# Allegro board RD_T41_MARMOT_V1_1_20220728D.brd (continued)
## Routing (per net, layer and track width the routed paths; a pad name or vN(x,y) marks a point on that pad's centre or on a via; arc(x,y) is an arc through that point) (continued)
SFC1_WP_IO2: length 24.6
  TOP w0.102: U6.U7 62.19,43.18 62.19,29.52 65.24,26.47 65.24,21.68 65.61,21.31 R167.1 66.41,21.31 R72.1
SFC_CS_N: length 27.2
  TOP w0.102: R26.1 52.27,22.46 51.04,23.68 51.04,27.13 51.88,27.97 U7.1 53.4,27.97 54.08,28.64 54.08,31.89 59.61,37.42 59.61,41.56 60.01,41.96 60.01,43.81 U6.T4
SFC_SCLK: length 22.9
  TOP w0.102: U6.R6 61.09,44.24 61.09,41.09 60.73,40.73 60.73,35.81 57.44,32.52 57.44,26.41 58.43,25.43 U7.6
SFC_SIO0: length 23.6
  TOP w0.102: U7.5 57.85,24.16 56.54,25.47 56.54,33.01 60.27,36.73 60.27,41.29 60.7,41.72 60.7,43.2 U6.U5
SFC_SIO1: length 21.9
  TOP w0.102: U6.R5 60.45,44.24 60.45,43.75 60.24,43.55 60.24,41.89 59.82,41.47 59.82,37.14 54.88,32.2 54.88,27.67 53.91,26.7 U7.2
SFC_SIO2: length 22.8
  TOP w0.102: U6.T5 60.79,43.75 60.46,43.42 60.46,41.77 60.03,41.34 60.03,36.9 55.73,32.6 55.73,26.73 54.42,25.43 U7.3
SFC_SIO3: length 19.7
  TOP w0.102: U6.T6 61.3,43.79 61.3,42.95 61.45,42.79 61.45,35.34 58.54,32.43 58.54,27.46 59.3,26.7 U7.7
SLCD_BLEN: length 3.5
  TOP w0.102: U24.16 108.39,66.74 ; 108.39,66.74 108.39,67.1 108.53,67.24 U24.15 ; 108.39,66.74 R276.1 106.75,66.06 R81.1
SLCD_BT656_D0: length 60.2
  TOP w0.102: R253.1 112.86,79.83 111.68,79.83 110.9,80.62 90.25,80.62 67.38,57.75 67.38,53.78 U6.A15
SLCD_BT656_D1: length 60.8
  TOP w0.102: R256.1 112.88,78.84 110.78,78.84 109.3,80.32 90.24,80.32 67.62,57.7 67.62,53.57 67.29,53.24 U6.B15
SLCD_BT656_D2: length 59.7
  TOP w0.102: R259.1 112.95,77.89 111.32,77.89 109.32,79.89 90.14,79.89 67.94,57.68 U6.A16
SLCD_BT656_D3: length 59.1
  TOP w0.102: R263.1 112.9,76.83 111.42,76.83 110.67,76.08 86.7,76.08 68.25,57.62 68.25,53.54 68.08,53.37 67.82,53.37 67.59,53.14 67.59,52.69 U6.C15
SLCD_BT656_D4: length 56.5
  TOP w0.102: R264.1 112.88,75.79 86.8,75.79 68.59,57.57 U6.A17
SLCD_BT656_D5: length 57.1
  TOP w0.102: U6.B16 68.16,53.03 68.46,53.34 68.88,53.34 68.99,53.45 68.99,57.61 86.19,74.81 112.92,74.81 R266.1
SLCD_BT656_D6: length 56.1
  TOP w0.102: U6.B17 68.96,53.03 69.26,53.33 69.26,57.52 85.55,73.8 112.92,73.8 R269.1
SLCD_BT656_D7: length 57.4
  TOP w0.102: R272.1 112.84,72.7 109.73,72.7 108.87,73.56 85.61,73.56 69.61,57.56 69.61,53.27 69.07,52.73 68.28,52.73 U6.C16
SLCD_CS: length 64.6
  TOP w0.102: R277.1 TP27.1 109.47,86.08 107.83,84.44 107.83,84.45 93.12,84.45 74.78,66.11 73.06,66.11 71.93,64.98 71.93,63.8 66.45,58.32 66.45,54.24 66.32,54.1 66.32,53.57 65.99,53.24 U6.B13
SLCD_CS_PD10: length 4.5
  TOP w0.102: J22.14 116.33,87.95 R277.2
SLCD_D0_PD00: length 4.6
  TOP w0.102: R253.2 114.8,80.39 116.75,78.45 J22.33
SLCD_D1_PD01: length 4.3
  TOP w0.102: R250.2 114.73,79.38 116.16,77.95 J22.34
SLCD_D2_PD02: length 4.1
  TOP w0.102: R258.2 114.69,78.36 115.6,77.45 J22.35
SLCD_D3_PD03: length 3.9
  TOP w0.102: R261.2 114.85,76.95 J22.36
SLCD_D4_PD04: length 3.8
  TOP w0.102: R262.2 114.57,76.45 J22.37
SLCD_D5_PD05: length 4
  TOP w0.102: J22.38 115.09,75.95 R266.2
SLCD_D6_PD06: length 4.2
  TOP w0.102: J22.39 115.97,75.45 114.81,74.29 R269.2
SLCD_D7_PD07: length 4.4
  TOP w0.102: J22.40 116.62,74.95 114.95,73.28 R271.2
SLCD_DC: length 65.8
  TOP w0.102: U6.C13 65.67,52.7 65.67,54.1 65.97,54.4 65.97,58.55 71.42,64 71.42,65.3 72.77,66.65 74.6,66.65 93.17,85.22 v1(106.92,85.22) ; R278.1 111.61,85.09 TP28.1 v1(109.06,85.06)
  BOTTOM w0.102: v1(109.06,85.06) 108.9,85.22 v1(106.92,85.22)
SLCD_DC_PD11: length 5
  TOP w0.102: R278.2 114.98,85.61 114.98,86.09 116.34,87.45 J22.15
SLCD_IOVDD: length 1.7
  BOTTOM w0.305: v1(116.96,91.7) 117.07,91.59 C198.1 C200.1
SLCD_LEDA: length 9.3
  TOP w0.279: 116.76,73.45 J22.43 ; 112.3,68.24 U24.8
  TOP w0.381: 112.3,68.24 112.8,68.24 C201.1 113.28,68.72 113.28,69.96 116.76,73.45
SLCD_LEDK: length 9.9
  TOP w0.249: U24.6 112.25,67.24 112.58,66.91 ; U24.5 112.5,66.74
  TOP w0.279: J22.47 116.83,71.45 ; J22.46 116.83,71.95 ; 116.87,72.76 117.06,72.95 J22.44 ; J22.45 116.83,72.45 ; J22.49 116.83,70.45 ; J22.48 116.83,70.95
SLCD_RDY: length 64.3
  TOP w0.102: U6.C14 66.29,52.73 66.29,53.12 66.53,53.36 66.53,53.99 66.67,54.13 66.67,58.21 72.26,63.8 72.26,64.98 73.16,65.88 74.88,65.88 93.1,84.1 TP29.1 110.01,84.09 R279.1
SLCD_RDY_PD12: length 5.4
  TOP w0.102: J22.17 v1(116.97,86.45) 116.82,86.45 R279.2
  BOTTOM w0.102: R257.1 116.96,86.47 v1(116.97,86.45)
SLCD_RST_PD09: length 4.3
  TOP w0.102: R275.2 114.78,87.08 116.15,88.45 J22.13
SLCD_TE: length 64.6
  TOP w0.102: R275.1 111.58,87.08 TP26.1 110.06,87.08 107.81,84.82 93.14,84.82 74.7,66.39 72.96,66.39 71.69,65.12 71.69,63.91 66.21,58.43 66.21,54.31 65.99,54.09 U6.A13
SLCD_VCI: length 1.6
  BOTTOM w0.305: C199.1 117.63,89.79 C197.1 116.97,90.68 v1(116.96,90.7)
SLCD_WR_BT656_PCLK: length 62
  TOP w0.102: U6.B14 66.75,53.14 66.75,53.91 66.89,54.06 66.89,58.13 72.5,63.74 72.5,64.87 73.25,65.61 74.91,65.61 90.25,80.95 112.92,80.95 112.94,80.93 R274.1
SLCD_WR_PD08: length 8.2
  TOP w0.102: v1(115.5,85.76) 115.5,86.04 116.41,86.95 J22.16 ; R273.2 v1(114.45,82.13)
  BOTTOM w0.102: v1(115.5,85.76) 114.45,84.71 v1(114.45,82.13)
SOC_0V8: length 52.7
  TOP w0.508: v1(79.07,47.35) 79.03,47.35 78.36,46.67 78.36,41.26 v1(77.36,40.26)
  BOTTOM w0.254: C16.1 84.81,54.49 C15.2 85.54,54.48 R6.2
  BOTTOM w0.508: J4.1 79.67,47.94 v1(79.07,47.35) ; 62.41,37.07 61.72,37.76 ; 62.41,37.07 61.56,37.07 ; 62.41,37.07 64.12,35.36 72.46,35.36 v1(77.36,40.26) ; 61.72,37.76 61.72,37.22 61.56,37.07 ; 61.72,37.76 R325.1 ; 61.56,37.07 53.27,37.07 52.06,38.28 R330.2
SOC_1V8: length 72.2
  TOP w0.33: v1(58.41,39.04) 58.41,39.27 58.42,39.29 R27.2
  L3_PWR w0.508: v1(53.51,38.1) 53.15,38.47 v1(51.24,38.47) ; v1(58.41,39.04) 58.65,39.28 66.83,39.28 69.67,36.44 71.36,36.44 v1(71.58,36.65)
  BOTTOM w0.381: v1(58.41,39.04) 58.74,38.71 R326.1
  BOTTOM w0.508: R84.1 55.75,55.29 55.75,57.37 56.31,57.93 60.9,57.93 R80.1 ; R84.1 v1(54.13,54.95) v1(53.82,55.26) ; R84.1 53.73,53.26 53.73,48.84 R331.2 ; R28.2 64.57,39.99 65.81,38.76 67.55,38.76 69.69,36.62 71.55,36.62 v1(71.58,36.65) 72.19,37.26 R329.1 ; R328.1 53.29,38.32 v1(53.51,38.1) 53.68,37.94 58.65,37.94 59.04,38.32 R326.1 ; R331.2 53.09,48.62 50.43,45.97 50.43,39.28 v1(51.24,38.47) ; R331.2 55.07,48.62 R44.1
SOC_3V3: length 54.3
  TOP w0.254: R60.2 v1(71.58,37.56) ; R56.2 v1(69.9,37.21)
  TOP w0.305: TP3.1 36.78,64.56 J3.2 36.78,69.42 R16.1
  L3_PWR w0.508: v1(49.37,57.31) 49.37,57.1 v1(49.66,56.8) 53.16,56.8 53.64,56.32 56.17,56.32 56.65,56.8 58.6,56.8 v1(58.67,56.88) ; v1(71.58,37.56) 71.23,37.21 v1(69.9,37.21) 69.81,37.21 67.1,39.92 v1(63.21,39.92) 55.41,39.92 v1(54.96,39.47) 50.36,39.47 v1(49.79,38.9)
  BOTTOM w0.305: R63.2 63.31,40.02 v1(63.21,39.92)
  BOTTOM w0.381: R58.2 66.1,42.68 R57.2 65.46,41.22 65.46,40.09 66.1,39.44 67.66,39.44 v1(69.9,37.21) 71.23,37.21 v1(71.58,37.56)
  BOTTOM w0.508: v1(58.67,56.88) R64.2 ; R327.1 v1(54.96,39.47)
SOC_DDR: length 2.3
  TOP w0.381: TP5.1 77.02,59.93 J5.2
SPEAK_EN_PB31: length 118.2
  TOP w0.102: R103.1 34.06,16.42 v1(46.53,28.89) ; v1(76.95,88.87) 76.39,88.3 76.39,84.07 74.65,82.33 74.65,75.97 71.55,72.87 70.66,72.87 70.01,72.22 68.41,72.22 63.8,67.62 v1(63.8,64.39) 63.8,63.18 64.12,62.86 64.12,53.12 U6.B10 ; R187.1 v1(71.21,88.41)
  BOTTOM w0.102: v1(63.8,64.39) 63.06,64.39 62.48,63.81 50,63.81 46.86,60.67 46.86,29.21 v1(46.53,28.89) ; v1(71.21,88.41) 71.77,88.97 76.85,88.97 v1(76.95,88.87)
SPI1_CLK: length 6
  TOP w0.102: R206.1 67.67,18.1 67.67,21.19 68.4,21.92 R120.2
SPI1_CLK_PA22: length 3.2
  TOP w0.102: R206.2 65.68,15.08 65.18,15.08 64.81,14.71 U21.26
SPI1_CS: length 3.6
  TOP w0.102: R123.2 64.59,19.02 65.75,17.86 65.75,17.2 R208.1
SPI1_CS_PA29: length 3
  TOP w0.102: R208.2 65.78,15.69 65.4,15.31 65.05,15.31 64.31,14.57 U21.27
SPI1_DR: length 7
  TOP w0.102: v1(64.11,19.38) 64.11,18.8 64.83,18.07 R203.1 ; v1(65.28,19.35) 65.12,19.52 65.12,21.5 64.78,21.83 R67.2
  BOTTOM w0.102: v1(65.28,19.35) 64.14,19.35 v1(64.11,19.38)
SPI1_DR_PA21: length 2.5
  TOP w0.102: U21.28 63.81,15.06 R203.2
SPI1_DT: length 9.1
  TOP w0.102: R200.1 63.9,18.47 v1(63.8,18.58) ; R82.2 66.76,22.26 67.38,21.65 67.38,18.7 v1(67.25,18.58)
  BOTTOM w0.102: v1(63.8,18.58) v1(67.25,18.58)
SPI1_DT_PA20: length 2.4
  TOP w0.102: U21.29 63.31,15.48 R200.2
SPK_OUTL: length 10.7
  TOP w0.249: U17.28 65.59,85.22 65.72,85.35
  TOP w0.305: 65.72,85.35 66.7,86.33 73.92,86.33 C154.1
SPKOUT_N: length 8.6
  TOP w0.33: U11.8 v1(32.71,6.88) D8.2 32.45,6.11 J10.1
  BOTTOM w0.33: R101.1 29.78,8.96 31.86,6.88 v1(32.71,6.88)
SPKOUT_P: length 6.2
  TOP w0.33: U11.5 v1(30.76,6.98) D9.2 31.2,6.17 J10.2
  BOTTOM w0.33: R95.1 29.71,8.04 v1(30.76,6.98)
STO: length 4.2
  TOP w0.102: TP55.1 56.75,80.88 U17.6
TD_N: length 46.3
  TOP w0.102: U6.U16 68,43.22 68,42.89 68.64,42.25 70.28,42.25 73.96,38.58 73.96,38.41 73.89,38.34 73.89,38.17 74.01,38.05 74.17,38.05 74.24,38.12 74.41,38.12 74.53,38 74.53,37.83 74.41,37.71 74.41,37.54 74.53,37.42 74.7,37.42 74.82,37.54 74.99,37.54 75.11,37.43 75.11,37.26 74.98,37.13 74.98,36.97 75.1,36.85 75.27,36.85 75.39,36.97 75.56,36.97 89.38,23.15 89.38,19.99 v1(89.26,19.86) ; R240.1 v1(93.91,12.77)
  BOTTOM w0.102: v1(89.26,19.86) 89.61,20.22 90.29,20.22 90.71,19.8 90.71,14.96 93.21,12.46 93.6,12.46 v1(93.91,12.77)
TD_P: length 46.4
  TOP w0.102: U6.T16 68.28,43.59 68.28,43 68.76,42.53 70.4,42.53 89.66,23.26 89.66,19.99 v1(89.79,19.86) ; R238.1 v1(93.91,11.87)
  BOTTOM w0.102: v1(89.79,19.86) 89.94,20.01 90.1,20.01 90.43,19.68 90.43,18.36 90.32,18.24 90.19,18.24 90.07,18.12 90.07,17.95 90.19,17.83 90.32,17.83 90.43,17.72 90.43,17.55 90.32,17.43 90.19,17.43 90.07,17.31 90.07,17.14 90.19,17.02 90.32,17.02 90.43,16.9 90.43,16.73 90.32,16.62 90.19,16.62 90.07,16.5 90.07,16.33 90.19,16.21 90.32,16.21 90.43,16.09 90.43,14.84 93.09,12.18 93.6,12.18 v1(93.91,11.87)
TEST_TE: length 2.4
  TOP w0.102: U6.L13 v1(66.96,46.21)
  BOTTOM w0.102: v1(66.96,46.21) 66.96,46.18 TP8.1
TX+: length 25.2
  TOP w0.254: J19.1 117.47,18.99 117.76,18.78 118.26,18.78 119.78,17.27 119.78,12.58 117.55,10.36 114.47,10.36 112.65,12.18 106.92,12.18 105.79,11.05 U23.9
TX-: length 25.2
  TOP w0.254: U23.11 105.98,13.59 106.79,12.78 108.37,12.78 108.74,13.16 109.39,13.16 109.76,12.78 112.85,12.78 114.75,10.88 117.35,10.88 119.27,12.79 119.27,17.05 118.07,18.25 115.77,18.25 J19.2
TX_N0: length 8.1
  TOP w0.102: U22.4 84.68,15.2 84.79,15.09 87.7,15.09 90.33,12.46 90.95,12.46 R214.1
TX_P0: length 8.1
  TOP w0.102: U22.3 84.68,14.7 84.79,14.81 87.58,14.81 90.21,12.18 90.95,12.18 R213.1
U0_RTS_PB21: length 98.1
  TOP w0.102: v1(97.51,70.77) 97.42,70.86 83.85,70.86 v1(83.76,70.76) ; TP22.1 98.84,53.02 v1(98.05,53.02) 97.61,53.02 97.06,53.57 93.96,53.57 93.42,53.04 69.73,53.04 69.08,52.38 U6.C17
  BOTTOM w0.102: v1(97.51,70.77) 97.51,53.56 v1(98.05,53.02) ; R76.1 55.36,74.83 61.97,68.22 66.04,68.22 68.12,66.14 72.77,66.14 77.4,70.76 v1(83.76,70.76)
U0_TXD_PB22: length 77.8
  TOP w0.102: v1(96.58,69.23) 96.52,69.28 v1(82.33,69.28) ; U6.D15 67.62,52.07 69.06,52.07 69.82,52.83 93.51,52.83 93.98,53.29 96.75,53.29 v1(97.12,52.92) TP23.1 ; R68.1 v1(69.56,64.76)
  BOTTOM w0.102: v1(69.56,64.76) 69.78,64.98 73.09,64.98 77.4,69.28 v1(82.33,69.28) ; v1(97.12,52.92) 97.28,53.08 97.28,68.53 v1(96.58,69.23)
UART1_RXD_PB24: length 51.4
  TOP w0.102: U6.F16 68.05,50.54 110.56,50.54 114.44,54.42 116.22,54.42 R292.2 R289.2
UART1_TXD_PB23: length 52.2
  TOP w0.102: U6.F15 67.62,50.77 110.47,50.77 114.35,54.65 116.18,54.65 R293.2 116.63,55.1 R290.2
USB_AVD08: length 3.1
  TOP w0.254: U6.R4 v1(59.81,44.26)
  BOTTOM w0.254: v1(59.81,44.26) 59.81,43.99 C74.1 61.1,43.62 C73.1 62.02,43.62 FB4.2
USB_AVD18: length 4.5
  TOP w0.254: U6.T3 v1(59.16,43.61)
  BOTTOM w0.305: v1(59.16,43.61) 59.14,43.59 59.14,41.89 C76.1
  BOTTOM w0.381: FB2.2 59.36,39.72 C77.1 59.36,41.67 C76.1
USB_AVD33: length 5.4
  TOP w0.254: U6.R3 v1(59.16,44.26)
  BOTTOM w0.305: C78.1 58.42,41.68 58.73,41.99 58.73,43.1 58.68,43.15 58.68,43.78 v1(59.16,44.26)
  BOTTOM w0.381: FB5.2 58.28,39.85 C79.1 58.28,40.78 C78.1
USB_DM: length 7
  TOP w0.13: R151.1 55.78,38.69 56.28,39.2 56.28,39.42 55.99,39.71 55.99,39.92 56.15,40.07 56.36,40.07 56.65,39.78 56.87,39.78 57.06,39.98 57.06,42.05 58.21,43.2 58.21,43.26 U6.U1
USB_DP: length 7
  TOP w0.13: U6.T2 58.51,43.61 58.51,43.07 57.37,41.93 57.37,39.85 56.09,38.58 R152.1
USB_ID: length 2.5
  TOP w0.102: R27.1 58.42,41.9 58.84,42.31 U6.U2
USB_VBUS: length 8.2
  TOP w0.254: U6.U3 59.18,42.98 59.18,42.21 59.01,42.03 59.01,38.91 57.34,37.24 R25.1
  TOP w0.381: R25.1 56.99,37.22 57.61,36.6
VCM: length 2.5
  TOP w0.254: U6.R2 v1(58.51,44.26)
  BOTTOM w0.305: C68.1 56.72,43.7 C67.1 57.95,43.7 v1(58.51,44.26)
WIFI_WAKE_HOST: length 10.8
  TOP w0.102: TP45.1 61.69,62.87 61.69,54.18 61.44,53.92 U6.B6
WKUP_PD31: length 15.5
  TOP w0.102: TP11.1 81.26,45.37 81.26,46.73 79.58,48.42 68.65,48.42 U6.J17
XTO: length 2.8
  TOP w0.102: TP53.1 61.59,76.28 U17.10
N14970173: length 3.5
  TOP w0.203: R2.2 31.64,86.2 C7.2 31.63,87.19 R3.2 31.64,88.19 U1.3
N15664622: length 2.1
  TOP w0.381: U1.4 C6.1 32.82,91.64 R1.2
N16749111: length 15.1
  TOP w0.203: R24.1 60.41,22.46 R26.2
  TOP w0.381: U7.8 61.09,27.97 62.11,26.96 C60.1 62.11,26.26 C64.1 62.11,23.2 R24.1
N16751575: length 4.8
  TOP w0.102: R32.1 54.43,52.36 52.34,52.36 Y2.3 50.92,51.7 C70.2
N16753264: length 14.1
  TOP w0.102: C75.1 12.71,64.18 R33.2 ; C75.1 11.68,63.18 11.68,62.05 10.68,61.05 SW1.5 SW1.1 ; C75.1 12.69,65.05 R34.1
N16757380: length 3.8
  TOP w0.102: R39.1 86.42,39.41 R37.1
N16760505: length 36.2
  TOP w0.13: R151.2 54.72,37.54 48.98,31.8 48.98,10.23 TP13.1 48.98,9.71 48.98,7.38 D3.2 48.98,6.48 48.98,5.8 48.81,5.63 J7.2
N16760513: length 36.2
  TOP w0.13: J7.3 49.46,5.63 49.29,5.8 49.29,6.48 D5.2 49.29,7.38 49.29,9.71 TP12.1 49.29,10.23 49.29,31.67 52.56,34.95 52.78,34.95 52.79,34.94 53,34.94 53.16,35.09 53.16,35.3 53.14,35.32 53.14,35.53 54.94,37.32 55.36,37.32
N16771643: length 8.4
  TOP w0.33: R92.2 16.7,8.6 R91.1 ; C105.2 v1(22.28,6.8)
  TOP w0.381: R91.1 v1(17.48,9.29)
  BOTTOM w0.381: v1(22.28,6.8) 19.4,6.8 17.48,8.72 v1(17.48,9.29)
N16771875: length 3
  TOP w0.305: R94.1 14.76,8.63 C106.1 15.64,8.63 R92.1
  TOP w0.381: R94.1 14.48,9.45 v1(14.25,9.22)
  BOTTOM w0.381: R93.1 14.58,9.56 v1(14.25,9.22)
N16774062: length 6
  TOP w0.381: R106.1 35.88,10.41 C113.1 31.94,10.41 31.41,9.89 U11.6
N16774094: length 1.7
  TOP w0.33: R105.1 30.76,14.73 U11.4
N16774098: length 0.8
  TOP w0.33: R105.2 30.63,16.74 C112.1
N16774118: length 0.8
  TOP w0.33: R104.2 C111.1
N16774180: length 2.8
  TOP w0.33: U11.1 32.71,14.48 R102.1 R103.2
N16774192: length 1.7
  TOP w0.33: U11.3 31.41,14.7 R104.1
N16775243: length 4.7
  BOTTOM w0.102: U10.3 16.47,15.35 15.84,14.72 13.55,14.72 R99.2
N16779173: length 19.9
  TOP w0.102: U6.E1 56.92,51.08 56.05,50.22 49.79,50.22 42.57,57.44 R50.2
N16859821: length 2.7
  TOP w0.102: R170.2 68.3,79.38 U17.19
N16859918: length 1.8
  TOP w0.102: U17.3 58.72,82.38 R172.1
N16859920: length 3.4
  TOP w0.254: U17.22 v1(67.86,80.88) 67.86,80.87 68.87,80.87 R173.2
  BOTTOM w0.254: v1(67.86,80.88) 67.85,80.88 C136.1
N16861141: length 2.5
  TOP w0.102: R144.1 5.17,11.95 4.84,12.27 U13.3
N16861143: length 2.6
  TOP w0.102: U13.4 4.84,14.32 5.4,14.88 R145.1
N16861165: length 2.4
  TOP w0.102: R147.1 89.89,5.09 89.49,4.69 U14.3
N16861167: length 2.5
  TOP w0.102: U14.4 87.6,4.69 86.97,5.33 R148.1
N16861179: length 6.1
  TOP w0.305: FB14.1 84.74,2.87 C124.1 85.67,2.87 C123.1 86.68,2.88 87.64,3.84 U14.1
  TOP w0.381: R130.1 86.68,2.72 86.68,2.88
N16861294: length 2.5
  TOP w0.102: R154.1 101.43,89.08 102.03,89.67 U15.3
N16861296: length 2.5
  TOP w0.102: R155.1 104.33,89.19 103.85,89.67 U15.4
N16861324: length 6
  TOP w0.305: FB15.1 107.7,91.07 C125.1 106.74,91.07 C126.1 104.39,91.07 103.84,90.52 U15.1
  TOP w0.381: 104.39,91.07 104.39,92.21 R131.1
N16861434: length 2.5
  TOP w0.102: U16.3 15.91,61.11 15.4,60.61 R157.1
N16861436: length 2.5
  TOP w0.102: R158.1 18.29,60.53 17.7,61.11 U16.4
N16861448: length 5.8
  TOP w0.33: U16.1 17.75,61.96 18.28,62.49 19.64,62.49 19.7,62.43 ; C128.1 C127.1 20.68,62.38 FB16.1
  TOP w0.381: R132.1 19.72,62.45 19.7,62.43 C128.1
N16861556: length 7.5
  TOP w0.305: 3.22,15.02 2.89,15.35 ; 3.22,15.02 3.22,15.35 ; 3.22,15.02 3.23,15.02 3.99,14.26 U13.1
  TOP w0.381: 3.22,15.69 2.88,15.35 ; 3.22,15.69 3.22,15.35 2.88,15.35 ; 3.22,15.69 C121.1 C122.1 3.22,18.09 FB13.1 ; 2.88,15.35 2.48,15.35 1.97,14.85 R129.1
N16862955: length 2.8
  TOP w0.305: R180.1 51.49,95.63 C146.1 50.58,96.19 C147.1 R184.1
N16863107: length 3.2
  BOTTOM w0.381: 73.42,85.52 U18.5
  BOTTOM w0.508: R183.1 70.28,85.52 C150.1 73.42,85.52
N16863121: length 5.5
  BOTTOM w0.102: R185.1 75.38,86.89 C152.1 74.55,84.38 75.33,83.6 U18.3
N16863211: length 5.5
  TOP w0.102: R191.1 54.14,84.99 C158.1 53.34,87.55 54.11,88.32 U20.3
N16871764: length 2.9
  TOP w0.305: R181.1 61.22,95.97 C148.1 60,96.25 C149.1 59.06,96.26 R182.1
N16876325: length 4.3
  TOP w0.381: J15.2 74.22,99.23 D14.2 74.65,98.34 U19.5
N16876337: length 4.2
  TOP w0.381: U19.8 72.7,98.45 D15.2 72.97,99.28 J15.1
N16876351: length 5
  TOP w0.381: U19.6 74,95.79 74.59,95.21 C155.1 77.47,95.21 R189.1
N16876358: length 2.1
  TOP w0.305: U19.4 74.65,90.23 R190.1
N16876368: length 0.9
  TOP w0.305: C154.2 R190.2
N16876378: length 0.8
  TOP w0.305: R188.2 73.8,89.06 C153.2
N16876406: length 3.3
  TOP w0.102: U19.1 72.7,90.48 R186.1 72.25,89.11 R187.2
N16876412: length 2.2
  TOP w0.305: U19.3 74,90.3 R188.1
N16900408: length 9.5
  BOTTOM w0.127: Q2.1 112.63,36.34 111.08,36.34 C164.2 111.05,36.34 R198.2 109,36.34 R239.2 108.98,34.21 108.64,33.86 108.64,33.06 R237.2
N16904771: length 3.8
  TOP w0.102: C175.2 70.67,14.18 Y3.3 70.05,13.57 R210.2 69.24,13.49 R209.1
N16904783: length 5.6
  TOP w0.102: C176.2 72.07,11.18 Y3.1 71.36,12.89 69.69,12.89 R210.1 69.28,12.56 R211.1
N17093743: length 1.8
  TOP w0.305: D2.1 34.51,69.99 R16.2
N17110008: length 1.2
  TOP w0.102: D23.1 13.98,70.25 R304.2
N17238740: length 1.9
  TOP w0.381: R90.2 21.22,8.6 R89.1 22.27,8.61 C105.1
N17269254: length 10.4
  TOP w0.102: SW5.5 SW5.1 11.52,82.09 R301.1
N17275101: length 1.1
  TOP w0.102: D24.2 13.69,80.37 R308.2
N17289134: length 5.5
  TOP w0.203: U2.1 26.81,67.57 26.17,68.21 R4.2 26.18,70.77 C12.1
N17289227: length 4.3
  TOP w0.203: C13.2 28.03,66.04 R7.1 26.83,66.04 R8.2 24.99,66.56 U2.5
N17291669: length 5.4
  BOTTOM w0.203: U4.1 87.27,65.28 87.93,65.95 C22.1 88.76,68.63 R10.2
N17291730: length 4.8
  BOTTOM w0.203: U4.5 89.3,64.44 R14.2 88.41,63.55 R12.1 87.05,63.56 C20.2
N17297008: length 5.4
  TOP w0.203: U5.1 26.59,76.58 25.68,77.49 C26.1 25.67,79.84 R11.2
N17297010: length 4.3
  TOP w0.203: U5.5 24.49,75.69 R15.2 26.37,75.02 R13.1 C24.2
N17502278: length 1.7
  TOP w0.102: U6.F13 66.64,50.43 v1(66.96,50.11)
  BOTTOM w0.102: R20.2 67.02,50.05 v1(66.96,50.11)
N17525430: length 3
  BOTTOM w0.381: R328.2 52.57,41.59 C63.1 52.57,43.54 FB6.1
N17525778: length 1.3
  BOTTOM w0.381: R325.2 61.72,42.22 FB4.1
N17525816: length 1
  BOTTOM w0.381: FB2.1 60.49,38.78 R326.2
N17525850: length 1.1
  BOTTOM w0.508: FB5.1 57.17,38.78 R327.2
N17560999: length 1.1
  BOTTOM w0.381: FB7.1 72.19,44.73 R329.2
N17611755: length 4.8
  BOTTOM w0.203: C15.1 85.54,55.52 R6.1 86.85,55.52 R9.2 88.86,56.25 U3.5
N17611809: length 5.3
  BOTTOM w0.203: R5.2 87.4,60.68 C19.1 87.4,58.1 86.69,57.39 U3.1
N17639490: length 1.2
  TOP w0.102: R267.2 109.65,64.92 109.65,66.03 U24.1
N17639502: length 2.7
  TOP w0.254: U24.12 109.65,69.37 109.3,69.71 109.3,70.71 C194.2
N17639539: length 1.4
  TOP w0.254: U24.10 110.65,70.04 C195.1
N17639549: length 2.6
  TOP w0.254: U24.9 111.15,69.34 111.35,69.55 111.35,70.78 C194.1
N17639559: length 1.5
  TOP w0.254: U24.11 110.15,69.98 C195.2
N17639566: length 2.6
  TOP w0.254: U24.13 107.94,68.24 C196.1 107.7,68.48 R260.1
N17641417: length 1.7
  TOP w0.508: R295.1 89.36,63.88 D21.2
N17641433: length 4.6
  TOP w0.102: R296.2 89.69,58.64 87.28,58.64 86.93,58.99 U25.3
N17672752: length 15.9
  TOP w0.102: U6.D14 66.95,52.05 66.95,53.78 67.13,53.96 67.13,57.96 73.43,64.26 TP10.1
N17678928: length 11.4
  TOP w0.102: U6.A11 64.55,53.82 64.55,63.39 R156.2 R153.1
N17679213: length 12.5
  TOP w0.102: R54.2 66.13,64.77 R55.1 65.6,63.47 65.6,59.3 64.76,58.46 64.76,54.05 64.99,53.82 64.99,53.52 64.69,53.21 U6.B11
N17680383: length 1.7
  TOP w0.102: U6.T15 v1(66.96,44.26)
  BOTTOM w0.102: v1(66.96,44.26) 67.24,44.26 R62.1
N17689049: length 15.7
  TOP w0.102: U6.C5 60.44,52.73 60.44,53.2 60.21,53.43 60.21,65.77 59.77,66.21 R77.2
N17689055: length 58.9
  TOP w0.102: v1(62.62,62.39) 62.42,62.18 62.42,53.56 62.09,53.23 U6.B7 ; v1(81.29,68.71) 81.29,68.83 83.59,71.13 100.03,71.13 105.12,66.04 R81.2
  BOTTOM w0.102: v1(62.62,62.39) 64.54,62.39 64.94,61.98 68.18,61.98 70.87,64.67 73.14,64.67 77.35,68.89 81.12,68.89 v1(81.29,68.71)
N17689058: length 33.3
  TOP w0.102: R83.2 72.07,76.73 v1(69.59,74.25) ; U6.C7 61.76,52.71 61.76,53.8 61.95,53.99 61.95,69.43 65.22,72.7 65.22,73.87 v1(65.04,74.05)
  BOTTOM w0.102: v1(69.59,74.25) 69.39,74.05 v1(65.04,74.05)
N17690769: length 23
  TOP w0.102: R86.2 65.58,72.68 62.19,69.29 62.19,53.79 U6.A7
N17690856: length 25.9
  TOP w0.102: U6.C8 62.42,52.7 62.42,53.23 62.66,53.48 62.66,61.83 62.99,62.16 62.99,62.53 62.47,63.04 62.47,68.09 68.38,74 R88.2
N17700250: length 3.4
  BOTTOM w0.508: R303.1 73.44,80.09 74.53,81.19 D22.2
N17700350: length 4.5
  BOTTOM w0.102: U27.1 78.5,75.11 C209.2 79.51,75.66 Y4.2
N17700378: length 4.6
  BOTTOM w0.102: U27.2 78.5,73.84 C210.2 79.64,73.16 Y4.1
N17705583: length 3.4
  TOP w0.102: U22.21 v1(78.78,15.2)
  BOTTOM w0.102: C187.1 78.82,15.24 v1(78.78,15.2) 78.16,15.2 77.76,15.6 ; 77.76,15.6 R234.2 ; 77.76,15.6 R298.2
N17705597: length 1.7
  TOP w0.102: R218.2 80.73,12.99 U22.26
N17705611: length 2
  TOP w0.102: R220.2 83.72,18.8 U22.9
N17705613: length 1.8
  TOP w0.102: R221.2 83.22,19.25 U22.10
N17705750: length 1.7
  TOP w0.102: R235.1 82.72,11.27 U22.30
N17705784: length 1.7
  TOP w0.102: R226.2 83.71,12.99 U22.32
N17705826: length 1.6
  TOP w0.102: U22.15 80.72,19.5 R212.2
N17705884: length 2.5
  TOP w0.254: U22.2 v1(85.17,14.2)
  BOTTOM w0.381: C185.1 84.52,13.36 C184.1 85.05,14.33 v1(85.17,14.2)
N17705928: length 2.6
  TOP w0.254: v1(82.22,12.34) 82.22,13 U22.29
  BOTTOM w0.381: C183.1 81.85,12.65 82.17,12.34 v1(82.22,12.34) 82.44,12.55 C182.1
N17706002: length 1.8
  TOP w0.102: R225.2 81.72,11.31 U22.28
N17706200: length 2.8
  TOP w0.102: R217.1 85.64,12.94 84.88,13.7 U22.1
N17706222: length 1.7
  TOP w0.381: U23.7 v1(96.62,12.32)
  BOTTOM w0.33: C179.2 96.58,12.28 v1(96.62,12.32)
N17706227: length 3.2
  TOP w0.457: U23.15 v1(103.66,18.67) ; U23.10 v1(103.66,12.32) ; U23.13 v1(103.66,16.13)
N17706250: length 1.7
  TOP w0.381: U23.5 v1(96.62,14.86)
  BOTTOM w0.33: C178.2 96.57,14.81 v1(96.62,14.86)
N17706256: length 1.8
  TOP w0.381: U23.2 v1(96.62,18.67)
  BOTTOM w0.33: v1(96.62,18.67) 96.59,18.7 C177.2
N17706349: length 5.5
  BOTTOM w0.102: R224.1 109.46,7.6 J19.11
N17706354: length 6.9
  BOTTOM w0.102: J19.13 109.28,21.79 R231.1
N17728418: length 2.9
  TOP w0.102: U6.D9 v1(63.06,52.06)
  BOTTOM w0.102: v1(63.06,52.06) 63.48,52.48 63.48,53.68 R21.2
N17861413: length 2
  TOP w0.203: U25.4 86.93,55.93 C214.1
N17864164: length 5
  BOTTOM w0.102: R285.2 88.3,48.07 90.56,48.07 90.85,48.36 U26.3
N17864213: length 1.8
  BOTTOM w0.203: C215.1 90.85,45.36 U26.4
N17919056: length 1.8
  BOTTOM w0.33: R96.1 26.69,8.11 C107.1 28.31,8.11 R95.2
N17919062: length 1.8
  BOTTOM w0.33: R101.2 28.3,8.88 C212.2 26.7,8.88 R312.1
N17919066: length 2.7
  BOTTOM w0.33: R96.2 25.51,8.14 R98.2 23.84,8.14 C108.1 23.03,8.12 R97.1
N17919088: length 2.7
  BOTTOM w0.33: R313.1 23.1,8.9 C193.2 23.82,8.89 R100.1 25.54,8.89 R312.2
N17957644: length 13.1
  TOP w0.102: R46.2 68.04,64.77 R321.1 68.04,63.7 67.57,63.22 67.57,60.5 65.18,58.12 65.18,54.31 65.46,54.03 65.46,53.16 U6.B12
N17957722: length 13.6
  TOP w0.102: R322.1 67.08,63.98 66.58,63.48 66.58,59.92 64.97,58.31 64.97,54.18 65.2,53.94 65.2,53.44 65,53.24 65,52.72 U6.C12
N17960615: length 21.9
  TOP w0.102: R229.2 42.36,58.78 50.66,50.48 55.99,50.48 56.9,51.39 58.31,51.39 58.62,51.08 U6.E2
N17962213: length 6.9
  TOP w0.102: R79.2 60.63,60.07 60.63,53.84 U6.A5
N17974466: length 1.5
  BOTTOM w0.508: R80.2 63.07,57.23 FB1.1
N17976184: length 1.1
  BOTTOM w0.381: FB3.1 54.95,52.95 R84.2
N17978297: length 4.1
  BOTTOM w0.381: R330.1 51.83,41.1 51.83,43.95 52.32,44.45 FB9.2
N17978317: length 1.7
  BOTTOM w0.508: R331.1 55.27,47.1 FB10.2
N18062125: length 5.7
  BOTTOM w0.381: 58.51,18.86 58.5,18.87 C190.1 58.5,20.67 U28.8 ; 58.51,18.86 R78.2 ; 58.51,18.86 C28.1 58.52,18.29 58.21,17.99 R73.1
N149702450: length 1.8
  TOP w0.381: U1.1 29.74,90.06 29.15,90.65 C1.1
N176395273: length 1.8
  TOP w0.254: R265.1 111.85,64.94 111.15,65.64 U24.4

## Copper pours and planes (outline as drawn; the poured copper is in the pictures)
12V_IN on TOP: 23.59,102.83 17.64,102.83 16.91,102.09 16.91,98.46 17.55,97.81 23.48,97.81 23.82,98.15 23.82,102.6
GND on BOTTOM: 124.49,2 124.05,0.95 123,0.51 2,0.51 0.95,0.95 0.51,2 0.51,103 0.95,104.05 2,104.49 123,104.49 124.05,104.05 124.49,103 ; 12 cut-outs
GND on L2_GND, L3_PWR: 2,0.51 0.95,0.95 0.51,2 0.51,103 0.95,104.05 2,104.49 123,104.49 124.05,104.05 124.49,103 124.49,2 124.05,0.95 123,0.51
VBUS_5V on TOP: 48.3,4.15 47.94,4.15 47.73,4.35 47.73,5.18 47.13,5.79 46.37,5.79 46.1,6.06 46.1,7.72 45.15,8.67 45.15,9.92 45.37,10.13 47.04,10.13 47.95,9.23 47.95,6.39 48.4,5.94 48.4,4.24
VBUS_5V on BOTTOM: 42.92,7.85 44.15,7.85 45.22,8.92 45.22,9.84 45.73,10.35 48.32,10.35 48.55,10.13 48.55,8.9 48.06,8.41 48.06,6.43 47.78,6.15 43,6.15 42.78,6.37 42.78,7.71
VCC_1V8 on TOP: 29.08,76.84 31.25,76.84 31.78,77.37 34.37,77.37 34.73,77.01 34.73,75.09 34.09,74.46 29.29,74.46 28.91,74.83 28.91,76.67
VCC_3V3 on TOP: 34.54,68.49 32.17,68.49 31.65,67.97 29.67,67.97 29.39,67.7 29.39,65.89 29.84,65.45 31.28,65.45 31.84,64.89 34.85,64.89 35.03,65.07 35.03,68
VCC_3V3 on TOP: 23.43,28.38 23.69,28.12 28.9,28.12 30.5,29.72 30.5,33.34 30.34,33.49 25.47,33.49 23.43,31.45
VCC_3V3 on TOP: 113.07,92.99 113.07,91.11 112.74,90.78 111.98,90.78 110.88,89.69 110.88,89.09 111.32,88.65 111.32,88.19 111.26,88.13 108.17,88.13 107.3,89.01 107.3,90.03 107.55,90.28 108.11,90.28 108.32,90.49 108.32,90.51 111.04,93.23 112.83,93.23
VCC_3V3 on TOP: 112.44,62.52 112.17,62.24 112.17,60.39 112.55,60.01 112.55,57.1 112.68,56.96 113.12,56.96 113.3,57.15 113.3,59.61 113.44,59.76 114.37,59.76 114.59,59.54 114.59,58.42 114.67,58.33 115.26,58.33 115.68,58.75 115.68,60.04 114.75,60.97 114.75,62.32 115.11,62.68 115.11,64.46 114.98,64.59 113.06,64.59 112.44,63.97
VCC_3V3 on BOTTOM: 26.61,68.28 21.1,62.76 21.1,60.72 22.28,59.53 25.95,59.53 30.51,54.97 30.51,33.91 28.71,32.1 28.71,31.51 29.08,31.13 31.81,31.13 31.84,31.17 34.2,31.17 34.47,31.43 34.47,64.64 35.03,65.2 35.03,67.87 34.62,68.28
VCC_3V3 on BOTTOM: 81.14,81.95 80.9,82.19 78.07,82.19 77.57,81.69 77.57,80.6 77.8,80.36 80.76,80.36 81.14,80.74
VCC_3V3 on BOTTOM: 109.93,35.53 112.55,35.53 112.92,35.15 112.92,32.77 112.54,32.39 110.01,32.39 109.64,32.76 109.64,35.24
VCC_3V3 on L3_PWR: 80.17,4.28 71.91,12.54 57.26,12.54 56.76,13.04 56.76,14.85 57.25,15.34 67.02,15.34 74.2,22.51 74.36,22.51 78.78,26.94 91.26,26.94 111.75,47.43 111.75,60.74 110.51,61.98 95.85,61.98 94.74,63.08 94.74,64.4 95.08,64.73 104.97,64.73 105.73,65.49 105.73,82.99 102.08,86.63 90.04,86.63 79.84,76.44 72.32,76.44 71.56,75.68 54.85,75.68 54.84,75.69 53.94,75.69 52.22,77.41 45.12,77.41 35.46,67.74 35.46,65.47 34.58,64.59 31.79,64.59 31.4,64.98 31.4,69.85 43.9,82.34 56.13,82.34 60.01,78.46 65.5,78.46 66.42,79.39 71.08,79.39 84.25,92.56 84.3,92.56 85.29,93.55 107.61,93.55 111.29,89.87 111.29,87.66 111.12,87.49 111.12,72.37 111.48,72 111.48,71.94 115.32,68.1 115.32,64.95 115.36,64.91 115.36,64 114.96,63.6 114.96,34.73 112.43,32.21 106.27,32.21 97.27,23.2 87.88,23.2 86.65,21.97 86.65,12.58 84.81,10.75 84.81,5.26 83.83,4.28
VCC_5V on TOP: 11.61,47.16 11.61,45.93 11.88,45.65 13.16,45.65 13.38,45.88 13.38,47.26 13.28,47.37 11.82,47.37
VCC_5V on TOP: 44.89,13.91 47.04,13.91 47.16,13.79 47.16,11.47 46.88,11.18 45.11,11.18 44.51,11.78 44.51,13.53
VCC_5V on TOP: 27.59,90.01 23.54,90.01 23.03,89.51 23.03,84.81 17.91,79.68 17.91,72.66 21.97,68.6 25,68.6 25.64,69.24 25.64,70.98 25.26,71.36 24.25,71.36 21.36,74.25 21.36,77.58 21.76,77.98 25,77.98 25.23,78.21 25.23,78.67 24.75,79.14 24.39,79.14 24.17,79.36 24.17,80.21 25.94,81.97 28.12,84.15 28.12,89.48
VCC_5V on TOP: 30.07,33.85 27.86,33.85 27.63,34.08 27.63,35.28 27.85,35.5 30.06,35.5 30.28,35.27 30.28,34.06
VCC_5V on TOP: 101.4,103.42 99.51,103.42 98.86,102.77 98.86,95.9 99.03,95.73 100.88,95.73 101.24,96.1 101.24,98.86 101.74,99.36 101.74,102.92 101.57,103.09 101.57,103.25
VCC_5V on BOTTOM: 55.62,7.09 51.56,11.15 45.34,11.15 44.81,11.69 42.24,11.69 42.06,11.87 42.06,13.7 41.84,13.91 39.78,13.91 36.89,11.02 29.25,11.02 22.41,17.86 22.41,27.26 8.59,41.08 8.59,73.26 30,94.66 96.31,94.66 98.98,97.33 100,97.33 100.64,96.69 100.64,93.04 97.85,90.25 84.07,90.25 83.52,89.7 83.52,88.63 95.74,76.4 104.79,76.4 108.01,73.18 108.01,71.61 107.37,70.97 105.33,70.97 102.8,73.5 96.56,73.5 94.61,71.55 94.61,61.33 92.24,58.96 88.22,58.96 88.15,59.03 88.15,59.72 89.05,60.62 89.05,61.08 92.21,64.24 92.21,66.35 91.74,66.82 88.68,66.82 88.54,66.96 88.54,67.66 88.68,67.8 89.18,67.8 89.39,68.02 89.39,69.28 89.4,69.29 89.4,76.92 80.88,85.44 77.47,85.44 77.17,85.15 75.87,85.15 75.75,85.27 75.75,85.77 76.17,86.2 76.17,87.39 77.26,88.48 77.26,89.41 77,89.68 35.5,89.68 13.94,68.12 13.94,49.86 28.33,35.47 28.33,33.31 27.93,32.9 27.93,20.65 32.77,15.81 52.68,15.81 57.31,11.18 57.31,7.19 57.21,7.09
VCC_12V on TOP: 27.08,102.46 30.63,102.46 32.02,101.07 32.02,94.07 31.05,93.1 31.05,92.04 30.93,91.92 30.37,91.92 30.25,92.04 30.25,93.34 26.9,96.69 26.9,102.28
VCC_DDR on BOTTOM: 82.51,65.39 78.74,61.61 78.74,59.65 79.24,59.15 80.37,59.15 80.97,59.76 80.97,60.94 83.37,63.34 84.18,63.34 84.64,63.81 84.64,65.3 84.56,65.39
VDDMEM on TOP: 65.82,51.69 61.5,51.69 61.28,51.47 61.28,51.1 61.32,51.05 65.76,51.05 65.94,51.23 65.94,51.57
VDDMEM on BOTTOM: 63.24,51.77 63.62,52.15 64.44,52.15 64.65,51.93 65.34,51.93 65.53,51.74 65.81,51.74 66.17,52.1 66.83,52.1 67.01,52.27 67.01,55.73 70.94,59.66 73.68,59.66 74.01,59.33 74.01,58.84 73.62,58.44 71.29,58.44 67.83,54.99 67.83,51.88 67.28,51.32 65.93,51.32 65.81,51.2 65.51,51.2 65.41,51.3 64.56,51.3 64.46,51.2 61.69,51.2 61.66,51.17 60.87,51.17 60.8,51.24 60.8,51.61 60.97,51.77
VDDMEM on L3_PWR: 66.01,51.21 67.88,53.08 67.88,54.47 69.6,56.19 71.6,58.19 72.59,58.19 72.88,58.48 72.88,59.54 72.72,59.7 69.89,59.7 64.73,54.53 61.76,54.53 60.86,53.64 60.86,51.52 61.18,51.21
VDDMSC0 on TOP: 109.41,40.28 112.47,40.28 112.61,40.14 112.61,39.54 112.44,39.37 109.36,39.37 109.25,39.49 109.25,40.12
VDDMSC0 on BOTTOM: 112.75,36.92 112.75,37.97 111.45,39.27 111.45,40.43 111.85,40.83 113.68,40.83 113.98,40.54 113.98,36.82 113.87,36.7 112.97,36.7
AK7755_AVDD on BOTTOM: 61.35,84.54 62.03,84.54 63.26,85.76 66.77,85.76 67.23,85.3 67.23,83.86 67.25,83.84 67.25,83.05 68.28,82.01 68.28,80.83 68.03,80.58 67.31,80.58 67.06,80.33 66.74,80.33 66.6,80.19 66.6,79.57 66.8,79.36 68.35,79.36 69.21,80.23 69.21,85.84 68.6,86.45 61.41,86.45 61.08,86.12 61.08,84.8
AK7755_IOVDD on BOTTOM: 60.86,78.48 68.75,78.48 70.23,79.96 70.23,82.33 70.4,82.5 71.51,82.5 72.06,81.96 72.06,77.82 68.61,74.38 63.89,74.38 60.54,77.73 60.54,78.16
CORE_0V8 on TOP: 60.65,49.66 60.24,49.25 60.24,46.64 61.55,45.32 64.44,45.32 64.58,45.46 64.58,45.81 64.34,46.05 61.68,46.05 61.03,46.7 61.03,48.71 61.32,49.01 65.72,49.01 65.88,48.85 65.88,47.73 66,47.62 66.38,47.62 66.58,47.82 66.58,49.18 66.11,49.66
CORE_0V8 on BOTTOM: outline of 90 points within 59.62,44.51 77.89,55.85
CORE_0V8 on L3_PWR: 70.77,54.41 70.77,51.71 68.79,49.74 60.49,49.74 59.99,49.24 59.99,45.17 62.42,42.74 69.86,42.74 73.98,46.86 73.98,51.75 74.36,52.13 75.9,52.13 78.06,54.3 78.06,55.16 77.84,55.39 77.79,55.39 77.49,55.68 72.04,55.68
DC_12V on TOP: 14.89,87.97 12.06,87.97 11.62,88.41 11.62,100.93 12.29,101.6 14.89,101.6 15.47,101.02 15.47,88.55
DDRVDD on TOP: 60.33,50.96 65.89,50.96 65.93,50.92 65.93,50.54 65.73,50.34 60.52,50.34 60.23,50.62 60.23,50.86
DDRVDD on BOTTOM: 58.59,51.18 60.45,51.18 60.6,51.03 61.71,51.03 61.75,51.06 66.63,51.06 66.63,51.06 67.26,51.06 68,51.8 68,54.59 71.22,57.81 73.6,57.81 73.88,57.53 73.88,56.85 73.53,56.51 71.73,56.51 68.89,53.66 68.89,51.08 68.3,50.49 62.01,50.49 61.88,50.36 58.61,50.36 58.5,50.47 58.5,51.1
DDRVDD on L3_PWR: 60.42,50.32 67.29,50.32 69.68,52.7 69.68,53.82 71.73,55.88 72.68,55.88 73.09,56.29 73.09,57.47 72.75,57.81 71.49,57.81 68.18,54.51 68.18,53.07 66.18,51.07 60.33,51.07 60.23,50.97 60.23,50.5
DVP_3V3 on TOP: 19.12,29.87 22.1,29.87 22.58,29.39 22.58,28.46 22.36,28.25 22.36,28.24 22.22,28.09 20.35,28.09 20.34,28.11 20.08,28.11 19.61,28.58 18.67,28.58 17.98,29.27 16.83,29.27 16.61,29.49 16.61,30.17 16.84,30.4 18.59,30.4
DVP_5V on TOP: 18.86,45.68 19.14,45.96 20.41,45.96 20.6,46.15 20.6,47.16 20.26,47.49 14.48,47.49 14.18,47.19 14.18,45.91 14.4,45.68
MIPI1_2LANE_3V3 on TOP: 37.4,34.25 36.33,34.25 35.88,33.81 31.3,33.81 31.04,33.55 31.04,32.71 31.28,32.46 34,32.46 34.55,33.01 37.35,33.01 37.69,33.35 37.69,33.96
MIPI1_2LANE_5V on TOP: 37.48,35.34 35.82,35.34 35.55,35.06 31.29,35.06 31.03,34.8 31.03,34.15 31.08,34.1 35.51,34.1 36.13,34.72 37.52,34.72 37.6,34.79 37.6,35.22
SLCD_IOVDD on TOP: 114.02,93.28 115.9,93.28 117.09,92.09 119.08,92.09 119.09,92.07 119.09,91.85 119.05,91.8 117.31,91.8 117.25,91.75 117.25,91.63 117.29,91.59 119.03,91.59 119.08,91.54 119.08,91.33 119.04,91.3 116.81,91.3 115.91,92.19 114,92.19 113.86,92.34 113.86,93.12
SLCD_LEDK on TOP: 112.44,65.83 113.02,65.24 114.52,65.24 117.03,67.75 117.03,72.83 116.9,72.96 116.8,72.96 115.1,71.26 115.1,68.74 113.38,67.02 112.55,67.02 112.44,66.91
SLCD_VCI on TOP: 113.96,91.81 115.4,91.81 116.11,91.1 119.08,91.1 119.11,91.07 119.11,90.84 119.07,90.81 117.31,90.81 117.25,90.76 117.25,90.65 117.31,90.6 119.07,90.6 119.1,90.57 119.1,90.34 119.06,90.3 116,90.3 115.35,90.95 113.98,90.95 113.87,91.06 113.87,91.72
SOC_0V8 on BOTTOM: 84.02,57.7 79.69,57.7 78.95,56.97 78.95,54.26 79.07,54.15 80.89,54.15 81.85,55.11 83.83,55.11 84.18,55.46 84.18,57.54
SOC_1V8 on TOP: 52.68,57.13 54.44,55.38 54.44,54.88 54.27,54.72 53.86,54.72 53.06,55.52 51.51,55.52 50.11,56.92 50.11,58.58 38.6,70.1 38.6,73.74 37.18,75.16 36.01,75.16 35.6,75.58 35.6,76.52 36.03,76.95 38.78,76.95 40.35,75.39 40.35,71.2 52.68,58.86
SOC_3V3 on TOP: 35.88,67.93 37.62,67.93 38.11,67.44 38.11,65.7 39.89,63.93 44.44,63.93 49.9,58.46 49.9,56.69 49.77,56.56 49.58,56.56 43.98,62.15 37.26,62.15 35.76,63.65 35.76,67.81
SOC_3V3 on BOTTOM: 50.37,45.49 50.33,45.45 50.33,39.55 50.05,39.26 50.05,38.82 49.92,38.68 49.6,38.68 49.38,38.91 49.38,49.17 50.48,50.28 50.48,52.45 49.73,53.2 49.73,54.9 49.17,55.47 49.17,57.55 49.26,57.65 49.97,57.65 50.12,57.5 50.12,56.07 50.76,55.43 50.76,53.82 51.56,53.02 51.56,49.47 50.37,48.28
SOC_DDR on BOTTOM: 74.65,60.02 74.65,56.96 74.78,56.83 75.71,56.83 76.17,57.29 76.17,58.45 76.73,59.01 77.53,59.01 77.87,59.35 77.87,60.35 77.45,60.76 75.4,60.76
N14970293 on TOP: 29.92,93.14 28.87,94.19 23.59,94.19 23.33,93.93 23.33,92.22 23.4,92.14 27.38,92.14 28.04,91.49 29.53,91.49 29.92,91.87 29.92,92.45
N16760739 on BOTTOM: 40.83,13.21 40.11,13.21 38.98,12.08 38.98,6.88 39.78,6.08 42.11,6.08 42.31,6.28 42.31,7.36 40.98,8.69 40.98,13.06
N17289243 on TOP: 31.4,70.92 29.09,70.92 28.4,70.23 27.55,70.23 27.28,69.96 27.28,69.34 27.43,69.18 29.43,69.18 29.68,69.44 31.42,69.44 31.58,69.6 31.58,70.74
N17291736 on BOTTOM: 83.48,68.48 86.23,68.48 86.98,67.73 86.98,66.99 86.88,66.9 84.86,66.9 84.86,66.91 82.74,66.91 82.67,66.98 82.67,67.67
N17297090 on TOP: 31.03,79.68 27.56,79.68 26.77,78.89 26.77,78.41 26.93,78.25 31.18,78.25 31.42,78.49 31.42,79.29
N17611937 on BOTTOM: 82.05,60.35 85.81,60.35 86.55,59.61 86.55,59.09 86.48,59.03 84.54,59.03 84.3,59.27 82.06,59.27 81.9,59.43 81.9,60.19
N17706227 on BOTTOM (solid shape): 103.97,18.75 103.97,10.84 104.17,10.64 106.16,10.64 106.49,10.3 106.49,8.42 106.17,8.1 103.2,8.1 102.5,8.8 101.38,8.8 101.15,9.03 101.15,9.97 102.36,11.18 102.36,18.58 102.72,18.94 103.77,18.94
N17706406 on BOTTOM (solid shape): 102.62,7.77 102.62,5.85 102.35,5.58 100.96,5.58 100.72,5.82 100.72,7.71 101.1,8.09 102.3,8.09

Small or netless copper shapes (teardrops, artwork), in the pictures only: 1 on TOP

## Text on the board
BOTTOM: Artwork L6_BOT
Package Geometry/Pastemask Bottom: Artwork Paste_bot
Ref Des/Silkscreen Bottom: EMMC_DS | TEST_TE | RTC_0V8 | Artwork Silk_bot
User.Comments: Artwork Solder_top | Artwork Solder_bot
TOP: Artwork L1_TOP
Package Geometry/Pastemask Top: Artwork Paste_top
Ref Des/Silkscreen Top: BOOTSEL0 | BOOTSEL1 | DC_12V_IN | OFF | RST | MIC | ON | VCC_12V | VCC_5V | SPK | DVP_MCLK | SOC_3V3 | SOC_1V8 | DVP_PCLK | VSYNC | HSYNC | USB | PWDN | MP_DVP_RST | SCK | SDK | CKN_D4 | CKP_D5 | P1_D3 | N1_D2 | P0_D1 | N0_D0 | IRCUT_2 | IRCUT_1 | OUTE1 | STO | CLKO | OUTE2 | XTO | SOC_DDR | SOC_0V8 | LED2 | LED1 | MOTOR | TRST | PWRON | RST_O | WKUP | KEY | D3 | D0 | D2 | CMD | ADC1 | D1 | CLK | RDY | CS | BT565 | TE | DC | SD_CARD | RJ45 | DVP | MIPI | MIPI_MCLK | DM | DP | PULSE2 | AK7755_LIN | PULSE1 | SDOUT2 | WIFI_WK_HOST | SDOUT3 | OUT3 | OUT2 | ADC3 | ADC2 | SD_PWR_EN | PHY_RST | ADC0 | U0_TXD | U0_RTS | IRCUT_P | IRCUT_N | Artwork Silk_top
L2_GND: Artwork L2_GND
L3_PWR: Artwork L4_GND
DIMENSION: fei.zhang | aeon,fzhang | 18130732656 | Artwork drill_drawing | RD_T41_MARMOT | 1.0 | 1.1 | haisong.ding | 2022-06-14 | 2022-07-28
User.13: FIGURE | SIZE | 7.99 | 15.75 | 23.62 | 25.2 | 31.5 | 35.0 | 35.43 | 51.18 | 60.0 | 70.08 | 125.98 | 39.37 | 127.95 | 47.24x19.69 | 118.11x78.74 | 125.98x39.37 | 145.67x39.37 | DRILL CHART: TOP to BOTTOM | ALL UNITS ARE IN MILS | PLATED | NON-PLATED | QTY | 1909 | 32 | 2 | 3 | 7 | 11 | 1 | 13 | 4
